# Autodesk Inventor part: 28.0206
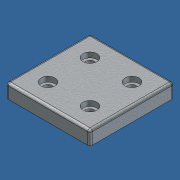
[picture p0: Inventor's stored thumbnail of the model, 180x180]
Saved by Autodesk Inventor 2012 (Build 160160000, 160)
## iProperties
Created: 2007-01
Part Number: 28.0206
Document SubType Name: Modeling
Designer: Andy Moles
Material: Aluminum-6061
Mass: 292.214 g
Surface Area: 236.663 cm^2
Volume: 107.828 cm^3
Density: 2.71 g/cm^3
Description: BEARING PLATE 90X90 IDLER SIDE
Stock Number: 21.1059 B&T PLATE 90X90 GD
Vendor: S
Author: Andy Moles
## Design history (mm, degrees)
sketch "Sketch1"
  geometry: L1 (-45, -45)-(45, -45); L2 (45, -45)-(45, 45); L3 (45, 45)-(-45, 45); L4 (-45, 45)-(-45, -45); L5 (-45, -45)-(45, 45); C1 r 4.5 at (-22.5, 22.5); C2 r 4.5 at (22.5, 22.5); C3 r 4.5 at (-22.5, -22.5); C4 r 4.5 at (22.5, -22.5); 2 further points
  constraints: 10 end point, 4 centre point, 2 parallel, 2 vertical alignment, 1 coincident, 1 horizontal, 1 midpoint, 1 perpendicular
  dimensions: "d0" = 90 distance of L2.end L3.end; "d1" = 90 distance of L3.end L1.start; "d2" = 9 diameter of C1; "d3" = 9 diameter of C2; "d4" = 22.5 distance from line of C1.centre L3; "d5" = 22.5 distance from line of L3 C2.centre; "d6" = 22.5 distance from line of C2.centre L2; "d7" = 22.5 distance from line of C1.centre L4; "d29" = 9 diameter of C3 (= d2); "d30" = 9 diameter of C4 (= d3); "d31" = 22.5 distance from line of C3.centre L1; "d32" = 22.5 distance from line of C4.centre L1
extrude "Extrusion1" new body sketch "Sketch1" distance "d8" = 15; taper "d9" = 0 deg
hole "Hole1" diameter "d12" = 15; stored, may be unused: countersink angle "d16" = 90 deg, drill point angle "d18" = 0 deg; dims "d10" = 10, "d11" = 10, "d13" = 6, "d14" = 4, "d15" = 2, "d17" = 5.5
hole "Hole2" diameter "d21" = 15; stored, may be unused: countersink angle "d25" = 90 deg, drill point angle "d27" = 0 deg; dims "d19" = 10, "d20" = 10, "d22" = 6, "d23" = 4, "d24" = 2, "d26" = 5.5
fillet "Fillet1" dims "d28" = 2.5
hole "Hole3" diameter "d35" = 15; stored, may be unused: countersink angle "d39" = 90 deg, drill point angle "d41" = 0 deg; dims "d33" = 10, "d34" = 10, "d36" = 6, "d37" = 4, "d38" = 2, "d40" = 5.5
hole "Hole4" diameter "d44" = 15; stored, may be unused: countersink angle "d48" = 90 deg, drill point angle "d50" = 0 deg; dims "d42" = 10, "d43" = 10, "d45" = 6, "d46" = 4, "d47" = 2, "d49" = 5.5
sketch "Sketch2"
  geometry: L1 (-45, -42.5)-(-45, 42.5) reference; L2 (-42.5, 45)-(42.5, 45) reference; C1 r 12 at (0, 18.5); 1 further point
  constraints: 1 centre point
  dimensions: "d51" = 24 diameter of C1; "d64" = 45 distance from line of C1.centre L1; "d65" = 26.5 distance from line of C1.centre L2
extrude "Extrusion2" cut sketch "Sketch2" distance "d52" = 10; taper "d53" = 0 deg
hole "Hole5" diameter "d56" = 30; stored, may be unused: countersink angle "d60" = 90 deg, drill point angle "d62" = 0 deg; dims "d54" = 10, "d55" = 10, "d57" = 6, "d58" = 4, "d59" = 2, "d61" = 9
body "Solid1"
